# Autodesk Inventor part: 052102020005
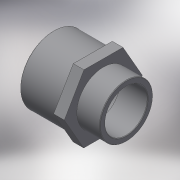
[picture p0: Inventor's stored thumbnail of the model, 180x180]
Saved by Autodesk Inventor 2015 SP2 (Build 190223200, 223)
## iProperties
Created: 2017-10
Part Number: 052102020005
Material: Generic
Description: PLASSON SOCKET NIPPLE THR-CE 25(20)-1/2"
Document SubType Name: Modeling
Designer: KIM
Density: 1 g/cm^3
Appearance: Default
Author: KIM
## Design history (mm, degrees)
derived "052102.ipt"
feature "Solid1::052102.ipt"
tag "TaggingFeature1"
body "Solid1"
other parameters: "d0" = 47, "d13" = 0, "d14" = 0.2, "d17" = 19, "d18" = 19.2, "d19" = 25, "d21" = 20.955, "d22" = 16, "d23" = 19, "d24" = 16.764, "d25" = 16, "d26" = -19, "R_" = 20.955, "B_" = 12, "L_" = 19, "lt_" = 16, "H_" = 47, "D_" = 25, "l_" = 16
